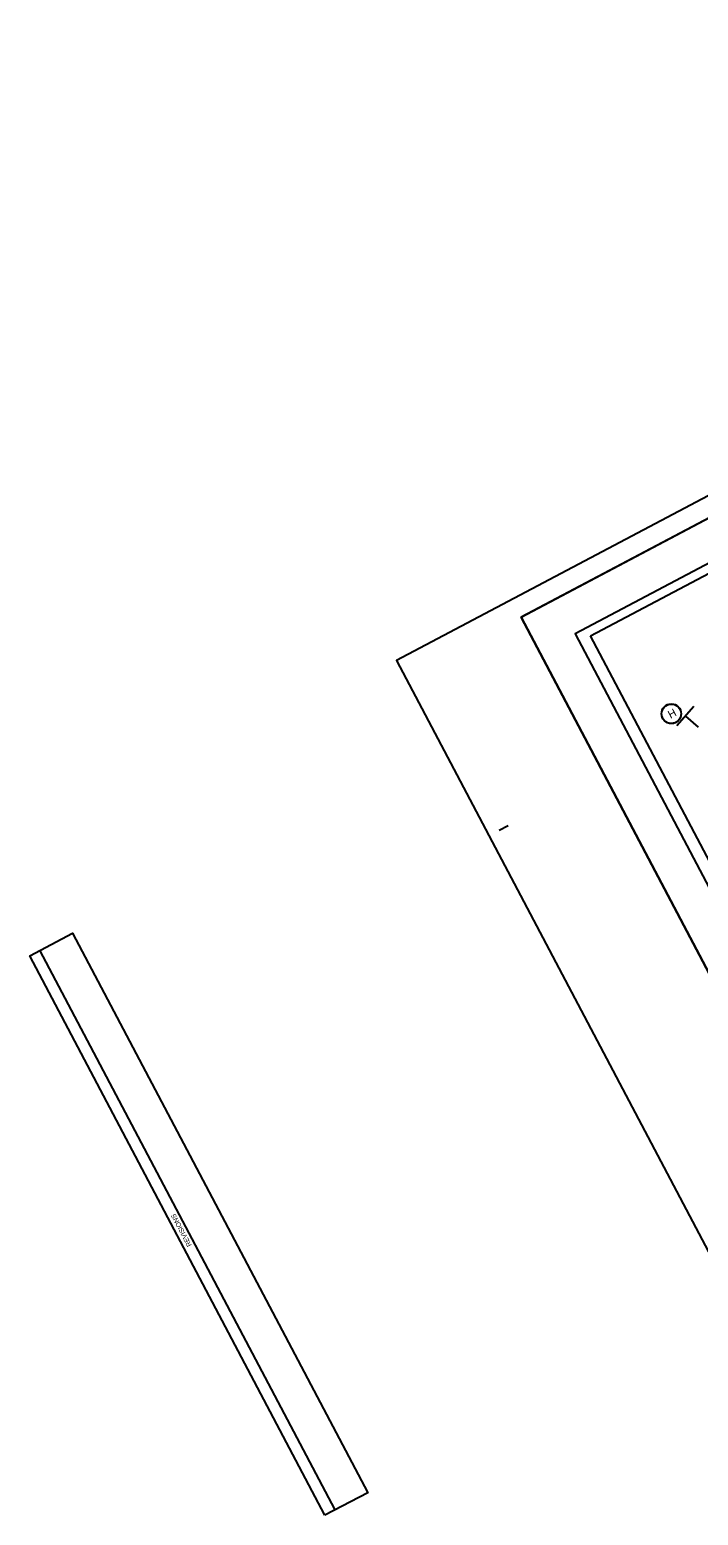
# Model space of a CAD drawing. Extents: x 1487176 to 2935813, y 497724 to 1002340.
# Drawn here: x 1487176 to 1488012, y 497841 to 499698 of the extents above; entities that cross this region are included whole.
import ezdxf

# ---------------------------------------------------------------- set-up
doc = ezdxf.new("R2010")
doc.units = 0
for name, color, linetype in [('DEV BORDER CELL', 7, 'Continuous'), ('DEV STATIONARY SIGN CELL', 7, 'Continuous'), ('Gray Area Fill Shapes', 7, 'Continuous'), ('Scratch_Level_0', 7, 'Continuous'), ('Scratch_Level_3', 7, 'Continuous'), ('Sheet Block Revision CELL', 7, 'Continuous'), ('Sheet Breakdown Map CELL', 7, 'Continuous'), ('Sheet Plot Border Outside CELL', 7, 'Continuous'), ('WZ OSDHWYEND CELL', 7, 'Continuous'), ('WZ OSDR CELL', 7, 'Continuous')]:
    doc.layers.add(name, color=color, linetype=linetype)

msp = doc.modelspace()

# ---------------------------------------------------------------- linework, layer by layer
at = {"layer": 'DEV BORDER CELL'}
for p, q in [((1487791.4, 498964), (1487791.4, 498964)), ((1487763.1, 498697.5), (1487774.1, 498703.3))]:
    msp.add_line(p, q, dxfattribs=at)
msp.add_lwpolyline([(1489116.9, 499664), (1487790.5, 498963.6), (1488280.8, 498035.1), (1489607.2, 498735.4)], close=True, dxfattribs=at)
at = {"layer": 'DEV STATIONARY SIGN CELL'}
for p, q in [((1488006.6, 498852.2), (1487985.4, 498827.7)), ((1487995.9, 498839.9), (1488011.8, 498826.2))]:
    msp.add_line(p, q, dxfattribs=at)
at = {"layer": 'Gray Area Fill Shapes'}
msp.add_circle((1487978.4, 498842.9), 12.2, dxfattribs=at)
at = {"layer": 'Scratch_Level_0'}
msp.add_lwpolyline([(1489096.1, 499596.4), (1487858.1, 498942.7), (1488301.6, 498102.6), (1489078.8, 498513), (1489023.6, 498617.6), (1489484.4, 498860.9)], close=True, dxfattribs=at)
at = {"layer": 'Scratch_Level_3'}
msp.add_lwpolyline([(1487790.5, 498963.6), (1488958.9, 499581.5), (1489116.9, 499664), (1489607.2, 498735.4), (1488280.8, 498035.1)], close=True, dxfattribs=at)
at = {"layer": 'Sheet Block Revision CELL'}
msp.add_line((1487557.9, 497848.3), (1487188.7, 498547.4), dxfattribs=at)
msp.add_lwpolyline([(1487545, 497841.5), (1487175.9, 498540.6), (1487229.4, 498568.9), (1487598.6, 497869.7)], close=True, dxfattribs=at)
at = {"layer": 'Sheet Breakdown Map CELL'}
msp.add_lwpolyline([(1487877.3, 498940.2), (1488411.8, 499222.4), (1488476.4, 499100.2), (1488513.4, 499119.8), (1488779.2, 498616.3), (1488207.7, 498314.6)], close=True, dxfattribs=at)
msp.add_lwpolyline([(1487877.3, 498940.2), (1488411.8, 499222.4), (1488476.4, 499100.2), (1488513.4, 499119.8), (1488779.2, 498616.3), (1488207.7, 498314.6)], close=True, dxfattribs=at)
at = {"layer": 'Sheet Plot Border Outside CELL'}
msp.add_lwpolyline([(1488148.3, 497936.8), (1489641, 498725), (1489127.4, 499697.7), (1487634.7, 498909.6)], close=True, dxfattribs=at)
at = {"layer": 'WZ OSDHWYEND CELL'}
msp.add_circle((1487978.3, 498843.1), 12.3, dxfattribs=at)

# ---------------------------------------------------------------- texts
at = {"layer": 'Sheet Block Revision CELL'}
msp.add_text('REVISIONS', height=6, rotation=117.8351, dxfattribs=at).set_placement((1487378.7, 498179))
at = {"layer": 'WZ OSDR CELL'}
msp.add_text('H', height=10, rotation=27.8351, dxfattribs=at).set_placement((1487977.3, 498836.6))

doc.saveas('drawing.dxf')
